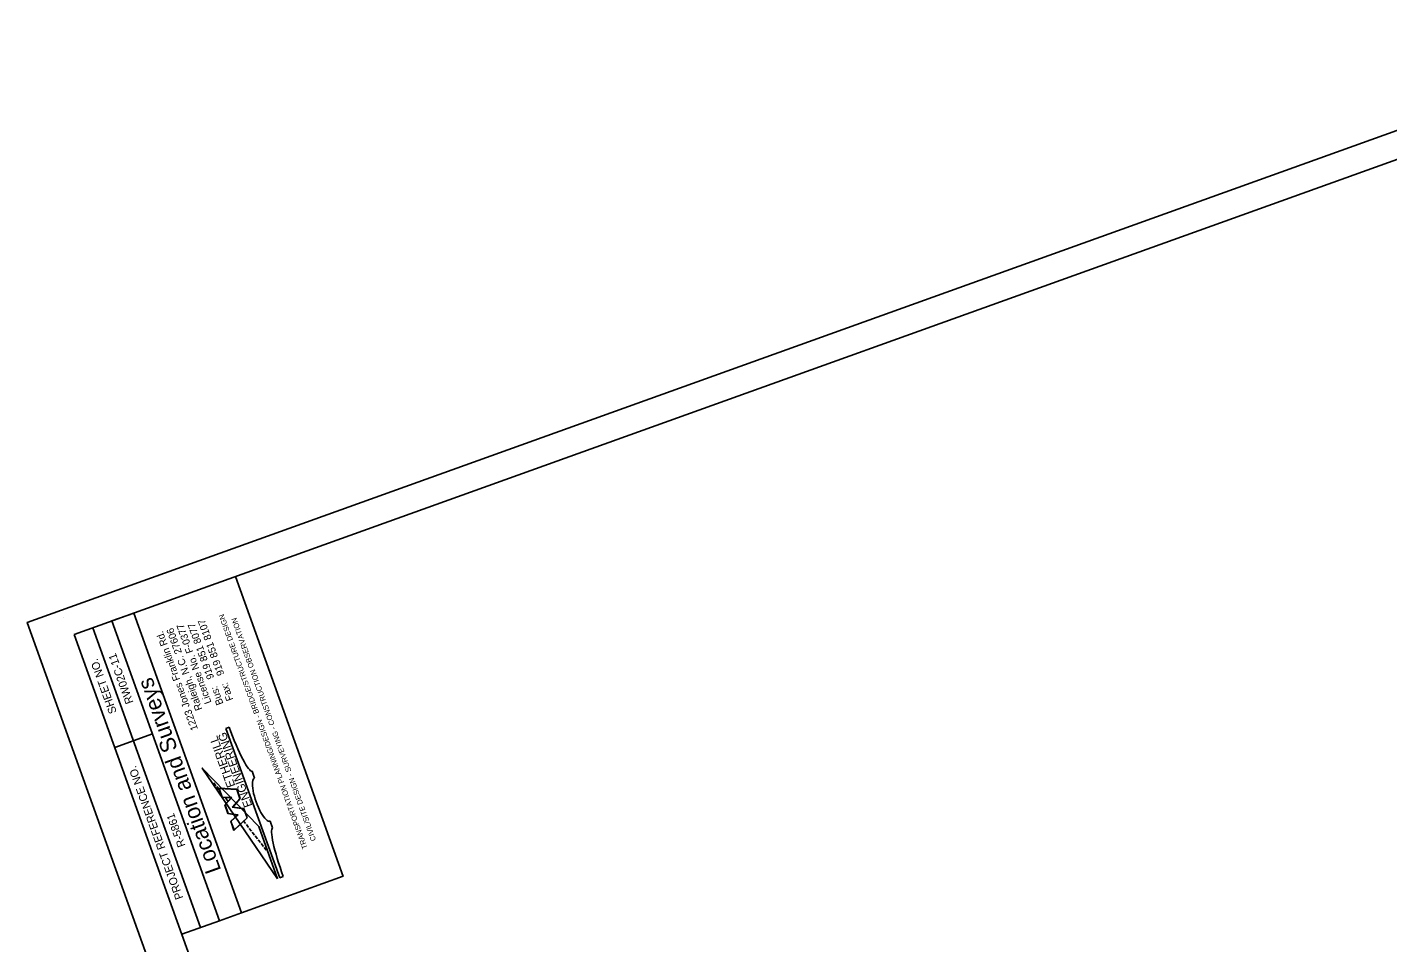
# Model space of a CAD drawing. Extents: x 480127 to 483680, y 514255 to 518588.
# Drawn here: x 480127 to 482009, y 517322 to 518588 of the extents above; entities that cross this region are included whole.
import ezdxf

# ---------------------------------------------------------------- set-up
doc = ezdxf.new("R2010")
doc.units = 0
for name, color, linetype in [('CTL Sheet Border CELL', 7, 'Continuous'), ('CTL Sheet Notes CELL', 7, 'Continuous'), ('Sheet Plot Border Outside CELL', 7, 'Continuous')]:
    doc.layers.add(name, color=color, linetype=linetype)

msp = doc.modelspace()

# ---------------------------------------------------------------- linework, layer by layer
at = {"layer": 'CTL Sheet Border CELL'}
for p, q in [((480564.2, 517413.5), (480415.3, 517828.2)), ((480177.2, 517772.1), (480177.2, 517772.1)), ((480177.2, 517772.1), (480177.2, 517772.1)), ((480127, 517764.7), (480127, 517764.7)), ((480366.9, 517342.7), (480218, 517757.3)), ((480248.1, 517591.7), (480300.2, 517610.4)), ((480423.6, 517363.1), (480564.2, 517413.6)), ((480340.8, 517333.4), (480392.9, 517352.1))]:
    msp.add_line(p, q, dxfattribs=at)
for points in [[(480191.8, 517748), (481314.5, 514621.4), (483503, 515407.2), (482380.4, 518533.8)], [(480392.9, 517352.1), (480244, 517766.7), (480274.7, 517777.7), (480423.6, 517363.1)]]:
    msp.add_lwpolyline(points, close=True, dxfattribs=at)
at = {"layer": 'CTL Sheet Notes CELL'}
for p, q in [((480406.3, 517619.9), (480401.6, 517618.2)), ((480401.6, 517618.2), (480476.6, 517411.4)), ((480388.1, 517538.9), (480385.1, 517542.9)), ((480441.6, 517549.4), (480438.2, 517558.8)), ((480392.2, 517533.7), (480389.2, 517537.6)), ((480392, 517535.3), (480396.5, 517522.9)), ((480416.9, 517533.6), (480392.5, 517534.9)), ((480392.5, 517534.9), (480396.7, 517523.2)), ((480421.4, 517521), (480416.9, 517533.6)), ((480421.8, 517521), (480417.1, 517533.9)), ((480396.5, 517522.9), (480409.3, 517522.2)), ((480396.7, 517523.2), (480410, 517522.4)), ((480409.3, 517522.2), (480400.3, 517512.3)), ((480400.3, 517512.3), (480404.7, 517500.2)), ((480410, 517522.4), (480400.7, 517512.2)), ((480400.7, 517512.2), (480405, 517500.5)), ((480404.5, 517517.9), (480401.5, 517521.8)), ((480410.7, 517509.2), (480421.4, 517521)), ((480426.6, 517506.9), (480410.7, 517509.2)), ((480411.4, 517509.4), (480421.8, 517521)), ((480426.8, 517507.2), (480411.4, 517509.4)), ((480431.1, 517494.4), (480426.6, 517506.9)), ((480431.5, 517494.3), (480426.8, 517507.2)), ((480404.7, 517500.2), (480417.9, 517498.3)), ((480405, 517500.5), (480418.7, 517498.5)), ((480417.9, 517498.3), (480408.6, 517489.6)), ((480408.6, 517489.6), (480413.1, 517477.1)), ((480418.7, 517498.5), (480408.9, 517489.5)), ((480408.9, 517489.5), (480413.2, 517477.7)), ((480413.1, 517477.1), (480431.5, 517494.3)), ((480413.2, 517477.7), (480431.1, 517494.4)), ((480429.1, 517486.4), (480426.1, 517490.3)), ((480466.6, 517480.4), (480463.2, 517489.8)), ((480433.2, 517481.1), (480430.2, 517485)), ((480437.3, 517475.8), (480434.3, 517479.8)), ((480441.4, 517470.6), (480438.4, 517474.5)), ((480445.5, 517465.3), (480442.4, 517469.3)), ((480449.6, 517460.1), (480446.5, 517464)), ((480453.7, 517454.8), (480450.6, 517458.7)), ((480457.8, 517449.5), (480454.7, 517453.5)), ((480476.6, 517411.4), (480481.3, 517413.1))]:
    msp.add_line(p, q, dxfattribs=at)
msp.add_lwpolyline([(480473.4, 517410.2), (480447.3, 517482.3), (480369.2, 517563.3)], close=True, dxfattribs=at)
msp.add_lwpolyline([(480417.1, 517533.9), (480416.7, 517533.9), (480392, 517535.3)], dxfattribs=at)
for centre, major_axis, ratio, start_param, end_param in [((480415, 517623), (-23.3, 64.2), 0.134146, 1.570796, 3.141593), ((480452.4, 517519.6), (-10.8, 29.8), 0.289474, 0, 3.141593), ((480489.9, 517416.2), (23.3, -64.2), 0.134146, 3.141593, 4.712389)]:
    msp.add_ellipse(centre, major_axis=major_axis, ratio=ratio, start_param=start_param, end_param=end_param, dxfattribs=at)
at = {"layer": 'Sheet Plot Border Outside CELL'}
msp.add_lwpolyline([(483680.1, 515077.8), (482419.8, 518587.9), (480127, 517764.7), (481387.3, 514254.6)], close=True, dxfattribs=at)

# ---------------------------------------------------------------- texts
at = {"layer": 'CTL Sheet Border CELL'}
for s, height, p in [('SHEET NO.', 11.07, (480251.1, 517640.6)), ('RW02C-11', 11.07, (480274.1, 517654.2)), ('Location and Surveys', 22.147, (480395.6, 517422.1)), ('PROJECT REFERENCE NO.', 11.074, (480343.1, 517383.8)), ('R-5861', 11.07, (480346.2, 517456.1))]:
    msp.add_text(s, height=height, rotation=109.7508, dxfattribs=at).set_placement(p)
at = {"layer": 'CTL Sheet Notes CELL'}
for s, height, rotation, p in [('1223 Jones Franklin Rd. ', 10, 109.7508, (480363.4, 517617.2)), ('Raleigh, N.C. 27606', 10, 109.7508, (480369.4, 517644.7)), ('License No. F-0377', 10, 109.7508, (480382.1, 517654)), ('Bus:   919 851 8077', 10, 109.7508, (480398.6, 517652.4)), ('Fax:   919 851 8107', 10, 109.7508, (480412.4, 517658.1)), ('TRANSPORTATION PLANNING/DESIGN - BRIDGE/STRUCTURE DESIGN', 7.333, 109.7508, (480515.1, 517452.8)), ('CIVIL/SITE DESIGN - SURVEYING - CONSTRUCTION OBSERVATION', 7.333, 109.7508, (480526.8, 517463.8)), ('ETHERILL', 11.67, 109.9099, (480415, 517538.8)), ('ENGINEERING', 11.667, 109.9099, (480438.6, 517511.3))]:
    msp.add_text(s, height=height, rotation=rotation, dxfattribs=at).set_placement(p)

doc.saveas('drawing.dxf')
